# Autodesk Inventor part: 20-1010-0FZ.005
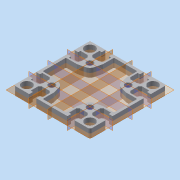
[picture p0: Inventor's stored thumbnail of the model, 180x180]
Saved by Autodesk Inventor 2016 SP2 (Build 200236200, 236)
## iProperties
Created: 2007-12
Document SubType Name: Modeling
Designer: Administrator
Density: 2.75 g/cm^3
Material: EN AW-6063 T66
Description: Profil 90x90 L
Mass: 55.331 g
Surface Area: 160.941 cm^2
Volume: 20.1204 cm^3
Part Number: 20-1010-0FZ.005
Appearance: Aluminium - flach - Version 1.1
M8x20_Stck: 0 oE
PV_Stck: 0 oE
Länge: 10.0 mm
Lieferantennr: 72401
Zeichnungsnr: 20-1010-0FZ.005
MiniTec_ID: 201010/0
Teileart: ART
Lieferant: MiniTec
Bezeichnung: Profil 90x90 L
Artikelnr: 201010/0
Bemerkung: eloxiert E6/EV1
M10x25_Stck: 0 oE
M12_Stck: 0 oE
AIMD_PARTNO: 201010/0
Title: Profil 90x90 L
Author: Administrator
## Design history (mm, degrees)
sketch "Skizze1"
  geometry: L1 (18.4, -44.7)-(18.4, -41); L2 (17.9, -40.5)-(16, -40.5); L3 (15.7, -40.2)-(15.7, -32); L4 (15.7, -32)-(18, -29.7); L5 (18, -29.7)-(27, -29.7); L6 (27, -29.7)-(29.3, -32); L7 (29.3, -32)-(29.3, -40.2); L8 (29, -40.5)-(27.1, -40.5); L9 (26.6, -41)-(26.6, -44.7); L10 (18.1, -45)-(-18.1, -45); L11 (42.5, -45)-(26.9, -45); L12 (-26.6, -44.7)-(-26.6, -41); L13 (-27.1, -40.5)-(-29, -40.5); L14 (-29.3, -40.2)-(-29.3, -32); L15 (-29.3, -32)-(-27, -29.7); L16 (-27, -29.7)-(-18, -29.7); L17 (-18, -29.7)-(-15.7, -32); L18 (-15.7, -32)-(-15.7, -40.2); L19 (-16, -40.5)-(-17.9, -40.5); L20 (-18.4, -41)-(-18.4, -44.7); L21 (45, -26.9)-(45, -42.5); L22 (44.7, -26.6)-(41, -26.6); L23 (40.5, -27.1)-(40.5, -29); L24 (40.2, -29.3)-(32, -29.3); L25 (32, -29.3)-(29.7, -27); L26 (29.7, -27)-(29.7, -18); L27 (29.7, -18)-(32, -15.7); L28 (32, -15.7)-(40.2, -15.7); L29 (40.5, -16)-(40.5, -17.9); L30 (41, -18.4)-(44.7, -18.4); L31 (45, 18.1)-(45, -18.1); L32 (44.7, 18.4)-(41, 18.4); L33 (40.5, 17.9)-(40.5, 16); L34 (40.2, 15.7)-(32, 15.7); L35 (32, 15.7)-(29.7, 18); L36 (29.7, 18)-(29.7, 27); L37 (29.7, 27)-(32, 29.3); L38 (32, 29.3)-(40.2, 29.3); L39 (40.5, 29)-(40.5, 27.1); L40 (41, 26.6)-(44.7, 26.6); L41 (45, 42.5)-(45, 26.9); L42 (26.9, 45)-(42.5, 45); L43 (26.6, 44.7)-(26.6, 41); L44 (27.1, 40.5)-(29, 40.5); L45 (29.3, 40.2)-(29.3, 32); L46 (29.3, 32)-(27, 29.7); L47 (27, 29.7)-(18, 29.7); L48 (18, 29.7)-(15.7, 32); L49 (15.7, 32)-(15.7, 40.2); L50 (16, 40.5)-(17.9, 40.5); L51 (18.4, 41)-(18.4, 44.7); L52 (-18.1, 45)-(18.1, 45); L53 (-18.4, 44.7)-(-18.4, 41); L54 (-17.9, 40.5)-(-16, 40.5); L55 (-15.7, 40.2)-(-15.7, 32); L56 (-15.7, 32)-(-18, 29.7); L57 (-18, 29.7)-(-27, 29.7); L58 (-27, 29.7)-(-29.3, 32); L59 (-29.3, 32)-(-29.3, 40.2); L60 (-29, 40.5)-(-27.1, 40.5); L61 (-26.6, 41)-(-26.6, 44.7); L62 (-42.5, 45)-(-26.9, 45); L63 (-45, 26.9)-(-45, 42.5); L64 (-44.7, 26.6)-(-41, 26.6)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; C1 r 3.75 at (22.5, -22.5); C2 r 3.75 at (-22.5, -22.5); C3 r 3.75 at (22.5, 22.5); C4 r 3.75 at (-22.5, 22.5); C5 r 5.85 at (37.15, -37.15); C6 r 5.85 at (-37.15, -37.15); C7 r 5.85 at (37.15, 37.15); C8 r 5.85 at (-37.15, 37.15); A1 r 0.3 centre (18.1, -44.7) between (18.1, -45) and (18.4, -44.7); A2 r 0.5 centre (17.9, -41) between (18.4, -41) and (17.9, -40.5); A3 r 0.3 centre (16, -40.2) between (15.7, -40.2) and (16, -40.5); A4 r 0.3 centre (29, -40.2) between (29, -40.5) and (29.3, -40.2); A5 r 0.5 centre (27.1, -41) between (27.1, -40.5) and (26.6, -41); A6 r 0.3 centre (26.9, -44.7) between (26.6, -44.7) and (26.9, -45); A7 r 0.3 centre (-26.9, -44.7) between (-26.9, -45) and (-26.6, -44.7); A8 r 0.5 centre (-27.1, -41) between (-26.6, -41) and (-27.1, -40.5); A9 r 0.3 centre (-29, -40.2) between (-29.3, -40.2) and (-29, -40.5); A10 r 0.3 centre (-16, -40.2) between (-16, -40.5) and (-15.7, -40.2); A11 r 0.5 centre (-17.9, -41) between (-17.9, -40.5) and (-18.4, -41); A12 r 0.3 centre (-18.1, -44.7) between (-18.4, -44.7) and (-18.1, -45); A13 r 2.5 centre (42.5, -42.5) between (42.5, -45) and (45, -42.5); A14 r 0.3 centre (44.7, -26.9) between (45, -26.9) and (44.7, -26.6); A15 r 0.5 centre (41, -27.1) between (41, -26.6) and (40.5, -27.1); A16 r 0.3 centre (40.2, -29) between (40.2, -29.3) and (40.5, -29); A17 r 0.3 centre (40.2, -16) between (40.5, -16) and (40.2, -15.7); A18 r 0.5 centre (41, -17.9) between (40.5, -17.9) and (41, -18.4); A19 r 0.3 centre (44.7, -18.1) between (44.7, -18.4) and (45, -18.1); A20 r 0.3 centre (44.7, 18.1) between (45, 18.1) and (44.7, 18.4); A21 r 0.5 centre (41, 17.9) between (41, 18.4) and (40.5, 17.9); A22 r 0.3 centre (40.2, 16) between (40.2, 15.7) and (40.5, 16); A23 r 0.3 centre (40.2, 29) between (40.5, 29) and (40.2, 29.3); A24 r 0.5 centre (41, 27.1) between (40.5, 27.1) and (41, 26.6); A25 r 0.3 centre (44.7, 26.9) between (44.7, 26.6) and (45, 26.9); A26 r 2.5 centre (42.5, 42.5) between (45, 42.5) and (42.5, 45); A27 r 0.3 centre (26.9, 44.7) between (26.9, 45) and (26.6, 44.7); A28 r 0.5 centre (27.1, 41) between (26.6, 41) and (27.1, 40.5); A29 r 0.3 centre (29, 40.2) between (29.3, 40.2) and (29, 40.5); A30 r 0.3 centre (16, 40.2) between (16, 40.5) and (15.7, 40.2); A31 r 0.5 centre (17.9, 41) between (17.9, 40.5) and (18.4, 41); A32 r 0.3 centre (18.1, 44.7) between (18.4, 44.7) and (18.1, 45); A33 r 0.3 centre (-18.1, 44.7) between (-18.1, 45) and (-18.4, 44.7); A34 r 0.5 centre (-17.9, 41) between (-18.4, 41) and (-17.9, 40.5); A35 r 0.3 centre (-16, 40.2) between (-15.7, 40.2) and (-16, 40.5); A36 r 0.3 centre (-29, 40.2) between (-29, 40.5) and (-29.3, 40.2); A37 r 0.5 centre (-27.1, 41) between (-27.1, 40.5) and (-26.6, 41); A38 r 0.3 centre (-26.9, 44.7) between (-26.6, 44.7) and (-26.9, 45); A39 r 2.5 centre (-42.5, 42.5) between (-42.5, 45) and (-45, 42.5); A40 r 0.3 centre (-44.7, 26.9) between (-45, 26.9) and (-44.7, 26.6); A41 r 0.5 centre (-41, 27.1) between (-41, 26.6) and (-40.5, 27.1); A42 r 0.3 centre (-40.2, 29) between (-40.2, 29.3) and (-40.5, 29); A43 r 0.3 centre (-40.2, 16) between (-40.5, 16) and (-40.2, 15.7); A44 r 0.5 centre (-41, 17.9) between (-40.5, 17.9) and (-41, 18.4); A45 r 0.3 centre (-44.7, 18.1) between (-44.7, 18.4) and (-45, 18.1); A46 r 0.3 centre (-44.7, -18.1) between (-45, -18.1) and (-44.7, -18.4); A47 r 0.5 centre (-41, -17.9) between (-41, -18.4) and (-40.5, -17.9); A48 r 0.3 centre (-40.2, -16) between (-40.2, -15.7) and (-40.5, -16); A49 r 0.3 centre (-40.2, -29) between (-40.5, -29) and (-40.2, -29.3); A50 r 0.5 centre (-41, -27.1) between (-40.5, -27.1) and (-41, -26.6); A51 r 0.3 centre (-44.7, -26.9) between (-44.7, -26.6) and (-45, -26.9); A52 r 2.5 centre (-42.5, -42.5) between (-45, -42.5) and (-42.5, -45); A53 r 2 centre (-29.241, 15.7) between (-29.241, 13.7) and (-28.765, 13.757); A54 r 7 centre (-22.5, 22.5) between (-20.834, 15.701) and (-15.701, 20.834); A55 r 2 centre (-15.7, 29.241) between (-13.757, 28.765) and (-13.7, 29.241); A56 r 1 centre (-12.7, 41) between (-12.7, 42) and (-13.7, 41); A57 r 1 centre (12.7, 41) between (13.7, 41) and (12.7, 42); A58 r 2 centre (15.7, 29.241) between (13.7, 29.241) and (13.757, 28.765); A59 r 7 centre (22.5, 22.5) between (15.701, 20.834) and (20.834, 15.701); A60 r 2 centre (29.241, 15.7) between (28.765, 13.757) and (29.241, 13.7); A61 r 1 centre (41, 12.7) between (42, 12.7) and (41, 13.7); A62 r 1 centre (41, -12.7) between (41, -13.7) and (42, -12.7); A63 r 2 centre (29.241, -15.7) between (29.241, -13.7) and (28.765, -13.757); A64 r 7 centre (22.5, -22.5) between (20.834, -15.701) and (15.701, -20.834)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
  constraints: 208 end point, 144 point on circle, 80 centre point
extrude "Extrusion1" new body sketch "Skizze1" taper "d1" = 0 deg; stored distance "do" = 10 (= Länge)
workplane "Arbeitsebene1"
workplane "Arbeitsebene2"
workplane "Arbeitsebene3"
workplane "Arbeitsebene4"
node "Volumenkörper1"
node "Volumenkörpern"
node "Oberflächenkörpern"
other parameters: "M8x20_Stck" = 0 [user parameter], "PV_Stck" = 0 [user parameter], "Länge" = 10 [user parameter; used in 1 equation term], "d17" = 0, "d18" = 0, "d19" = 0, "d20" = 0, "d21" = 0, "d22" = 0, "M10x25_Stck" = 0 [user parameter], "M12_Stck" = 0 [user parameter]
